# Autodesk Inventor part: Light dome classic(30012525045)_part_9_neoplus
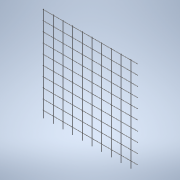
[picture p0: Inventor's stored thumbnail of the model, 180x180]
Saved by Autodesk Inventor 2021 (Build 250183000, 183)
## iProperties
Created: 2026-04
Part Number: Light dome classic(30012525045)_part_9_neoplus
Material: Generic
Catalog Web Link: www.3dfindit.com
Description: Light dome classic_part_9_neoplus-
Vendor: KINGSPAN
Document SubType Name: Modeling
Designer: psAdmin
Manufacturer: KINGSPAN
Mass: 383.147 g
Surface Area: 3074.77 cm^2
Volume: 383.147 cm^3
Density: 1 g/cm^3
Appearance: PSOLRGB-255-255-255
Category: PARTsolutions
Company: KINGSPAN
Title: Light dome classic(30012525045)_part_9_neoplus
Author: Cadenas PARTsolutions
PSOL_IDENT_0: {$CADENAS_DATA/23d-libs/kingspan_kla/light_dome_classic_neoplus/parts/part_9.prj},278 {VTYP=3D},{NB=
PSOL_IDENT_1: Light dome classic(30012525045)_part_9_neoplus},{LINA=Light dome classic(30012525045)_part_9_neoplus
PSOL_IDENT_2: },{NN=Light dome classic_part_9_neoplus},{DATE=15.07.2024 10:56:16},{GEOMDATE=28.06.2024 12:22:18},{
PSOL_IDENT_3: VERSION=},{LINEID=10},{WBVAR=LODLEVEL,L,W,DP,OP},{WBNUMERIC=W}  {NB=Light dome classic(30012525045)_
PSOL_IDENT_4: part_9_neoplus},{LINA=Light dome classic(30012525045)_part_9_neoplus},{KT=DUMMY},{IDNR=},{PN=Light d
PSOL_IDENT_5: ome classic},{LODLEVEL=300},{L=125},{W=250},{WX=125,250,300},{LX=1250},{XWX=2500},{DP=4},{OPX='5','P
PSOL_IDENT_6: neumatic - NRWG F.6 LK'},{OP=5},{DRIVE=1},{DPX='1', 'Natural ventilation', '2' , 'NSHEV (natural smo
PSOL_IDENT_7: ke, heat exhaust ventilation)', '3', 'Fixed','4','NSHE'}
NB: Light dome classic(30012525045)_part_9_neoplus
NN: Light dome classic_part_9_neoplus
NBSYN: $PN.($LODLEVEL.$L.$W.$DP.$OP.)_part_9_neoplus
LINA: Light dome classic(30012525045)_part_9_neoplus
CATALOG: Light + Air
PN: Light dome classic
LODLEVEL: 300
L: 125
W: 250
DP: NSHE
OP: Pneumatic - NRWG F.6 LK
SUPPLIER: KINGSPAN
ARTICLENO: Light dome classic(30012525045)_part_9_neoplus
BOMINFO: Light dome classic(30012525045)_part_9_neoplus
CREATOR: CADENAS GmbH
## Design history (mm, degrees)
sketch "Sketch_8"
  geometry: C1 r 2.5 at (475, 263.34); 1 further point
  constraints: 1 centre point
extrude "Extrusion1" join sketch "Sketch_8" stored distance "d0" = 2225; taper "d1" = 0 deg
sketch "Sketch_1"
  geometry: C1 r 2.5 at (-1100, 268.32); 1 further point
  constraints: 1 centre point
extrude "Extrusion2" join sketch "Sketch_1" stored distance "d2" = 975; taper "d3" = 0 deg
sketch "Sketch_2"
  geometry: C1 r 2.5 at (375, 263.34); 1 further point
  constraints: 1 centre point
extrude "Extrusion3" join sketch "Sketch_2" stored distance "d10" = 2225; taper "d11" = 0 deg
pattern_linear "Rectangular Pattern2" dims "d14" = 100, "d17" = 0
sketch "Sketch_9"
  geometry: L1 (-10, -278.32)-(10, -278.32); L2 (10, -278.32)-(10, -258.32); L3 (10, -258.32)-(-10, -258.32); L4 (-10, -258.32)-(-10, -278.32)
  constraints: 8 end point
extrude "Extrusion4" cut sketch "Sketch_9" stored distance "d18" = 220; taper "d19" = 0 deg
sketch "Sketch_10"
  geometry: L1 (-500, 522.5)-(-500, -522.5); L2 (-500, -522.5)-(0, -522.5); L3 (0, -522.5)-(0, 522.5); L4 (0, 522.5)-(-500, 522.5)
  constraints: 8 end point
extrude "Extrusion5" cut sketch "Sketch_10" distance "d20" = 2635; taper "d21" = 0 deg
node "IP_9_XY"
node "IP_9_YZ"
node "IP_9_ZX"
node "IP_9_X"
node "IP_9_Y"
node "IP_9_Z"
node "IP_9_Center"
body "Solid1"
pattern_linear "Rectangular Pattern1" dims "d6" = 100, "d9" = 0
